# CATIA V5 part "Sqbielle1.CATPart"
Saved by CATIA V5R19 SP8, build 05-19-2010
Part number: Sqbielle1
Publications: "Droite.3", "Droite.2", "Plan.1"
Bounding box of the stored display mesh (mm): x 0 to 0, y 0 to 20, z 0 to 590
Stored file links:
  F:\Travail\2e année\IAO\Projetsave\Sqbielle1.CATPart
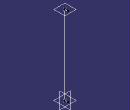
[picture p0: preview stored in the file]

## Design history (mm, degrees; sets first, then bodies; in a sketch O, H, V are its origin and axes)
Set1
  Point1: (0, 0, 0)
  Point2: (0, 0, 590)
  Line1: type PtPt, FirstPoint Point1, SecondPoint Point2
  Line2: type Normal, RefPoint Point1, RefSkin zx-plane, Start 0, End 20
  Line3: type PtDir, RefPoint Point2, Direction zx-plane, Start 0, End 20
  Plane1: type Offset, RefPlane xy-plane, Offset 590
Body1 (main body)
